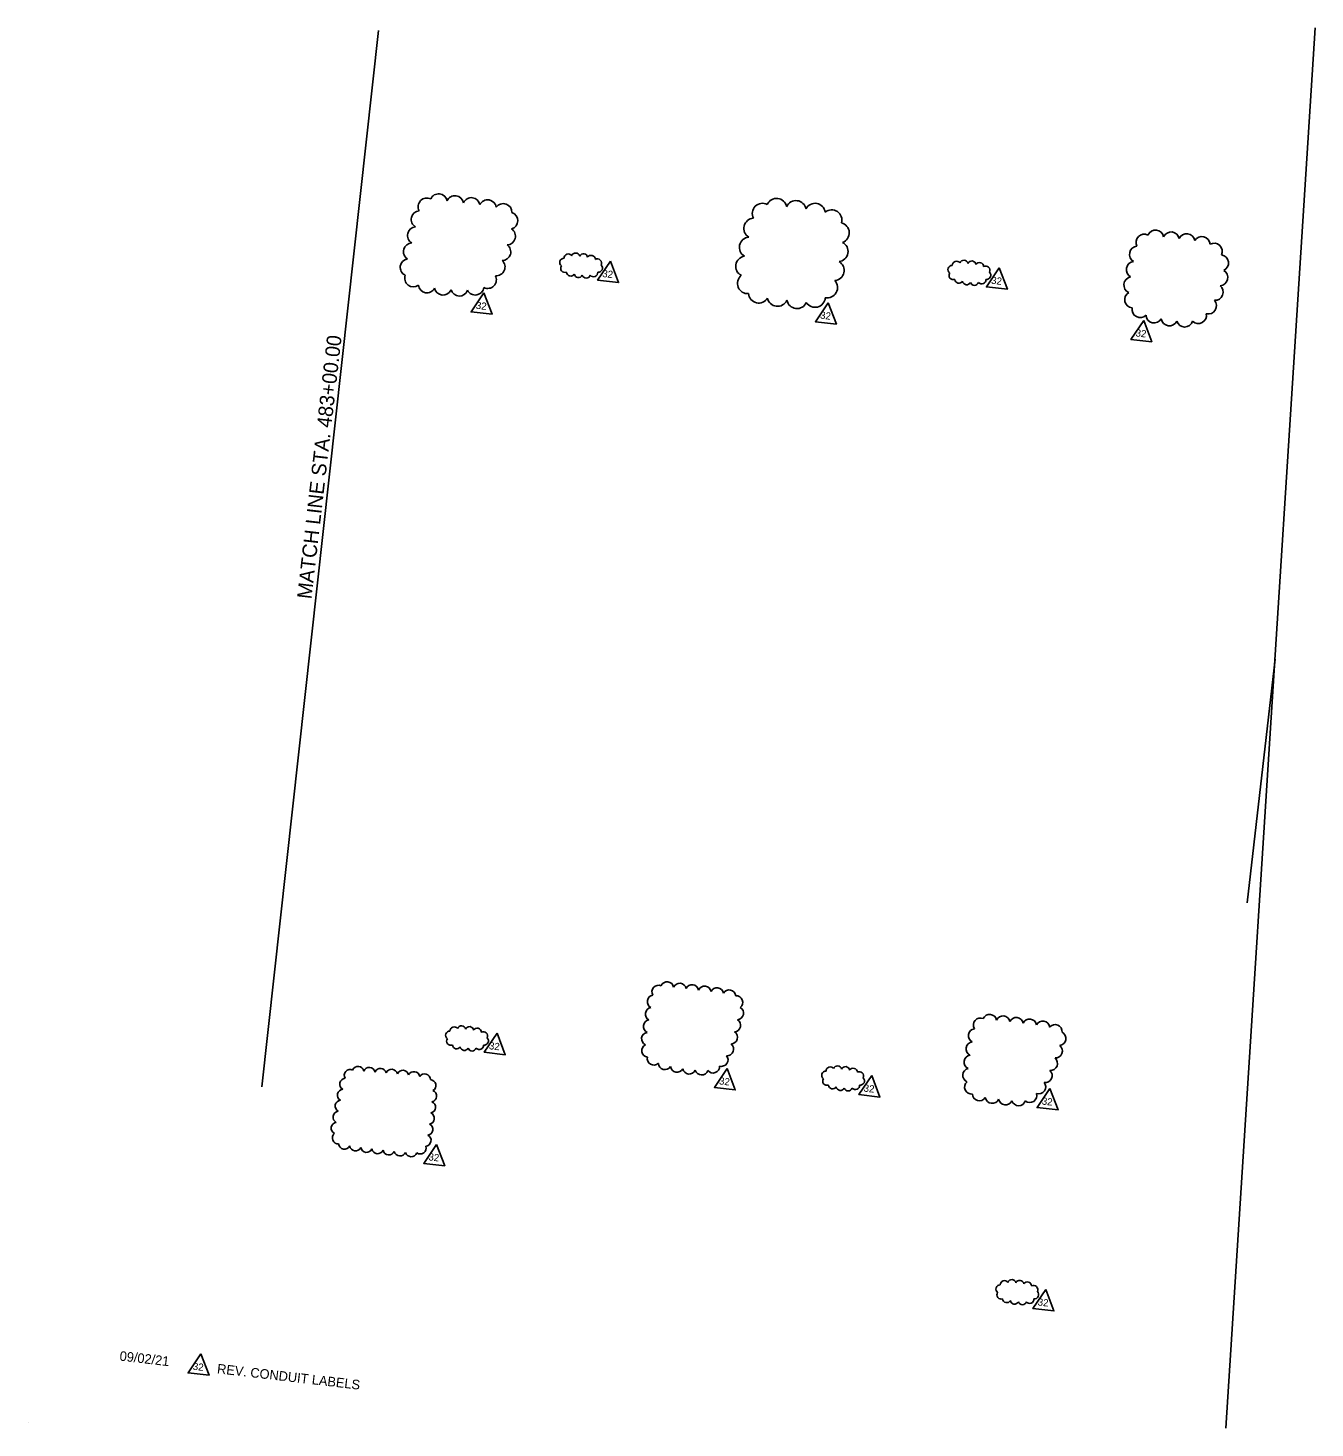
# Model space of a CAD drawing. Extents: x 926540 to 927877, y 636188 to 637075.
# Drawn here: x 926540 to 927245, y 636308 to 637075 of the extents above; entities that cross this region are included whole.
import ezdxf

# ---------------------------------------------------------------- set-up
doc = ezdxf.new("R2010")
doc.units = 0
for name, color, linetype in [('ActivePointCell_dp', 7, 'Continuous'), ('AdhocPoint_dp', 7, 'Continuous'), ('Cloud_dp', 7, 'Continuous'), ('MatchLines_dp', 7, 'Continuous'), ('ScratchEle_dp', 7, 'Continuous'), ('TextLabel', 7, 'Continuous'), ('TextNotes', 7, 'Continuous')]:
    doc.layers.add(name, color=color, linetype=linetype)

msp = doc.modelspace()

# ---------------------------------------------------------------- linework, layer by layer
at = {"layer": 'ActivePointCell_dp'}
msp.add_line((927223.55, 636729.15), (927208.28, 636595.55), dxfattribs=at)
at = {"layer": 'AdhocPoint_dp'}
msp.add_line((926539.98, 636310.75), (926539.98, 636310.75), dxfattribs=at)
at = {"layer": 'Cloud_dp'}
for points in [[(926859.18, 636947.3), (926852.17, 636936.9), (926863.65, 636935.58)], [(927072.35, 636943.6), (927065.33, 636933.2), (927076.81, 636931.88)], [(926789.89, 636929.87), (926782.88, 636919.48), (926794.36, 636918.16)], [(926978.6, 636924.49), (926971.59, 636914.1), (926983.06, 636912.78)], [(927151.52, 636914.77), (927144.5, 636904.38), (927155.98, 636903.06)], [(926797.06, 636524.03), (926790.05, 636513.64), (926801.53, 636512.32)], [(926923.19, 636504.75), (926916.18, 636494.36), (926927.65, 636493.04)], [(927002.47, 636500.82), (926995.46, 636490.43), (927006.93, 636489.11)], [(927100.12, 636493.71), (927093.11, 636483.32), (927104.58, 636482)], [(926763.9, 636463.12), (926756.89, 636452.73), (926768.37, 636451.41)], [(927097.85, 636383.57), (927090.84, 636373.17), (927102.32, 636371.85)]]:
    msp.add_lwpolyline(points, close=True, dxfattribs=at)
for centre, radius, start, end in [((926765.05, 636979.43), 4.75, 10.93299, 155.93299), ((926758.56, 636977.14), 4.75, 62.90771, 207.90771), ((926774.05, 636978.39), 4.75, 10.93299, 155.93299), ((926783.04, 636977.35), 4.75, 10.90569, 155.90569), ((926791.95, 636976.14), 4.75, 8.62888, 153.62888), ((926800.48, 636974.06), 4.75, 358.88682, 143.88682), ((926942.58, 636973.4), 5.61, 62.36437, 207.36437), ((926950.3, 636976.09), 5.61, 10.93299, 155.93299), ((926960.93, 636974.86), 5.61, 10.93299, 155.93299), ((926971.43, 636973.37), 5.61, 7.87137, 152.87137), ((926754.77, 636970.19), 4.75, 94.93587, 239.93587), ((926803.71, 636969.47), 4.74, 286.35637, 71.35637), ((926937.97, 636965.23), 5.61, 93.88155, 238.88155), ((926980.53, 636969.78), 5.61, 344.15324, 129.15324), ((926752.74, 636961.35), 4.75, 94.16753, 239.16753), ((926802.42, 636960.97), 4.75, 271.46132, 56.46132), ((926984.52, 636962.82), 5.61, 290.41714, 75.41714), ((927151.83, 636957.6), 4.51, 62.88116, 207.88116), ((927158, 636959.78), 4.51, 10.93299, 155.93299), ((927166.56, 636958.79), 4.51, 10.93299, 155.93299), ((927175.11, 636957.81), 4.51, 10.93276, 155.93276), ((926750.51, 636952.53), 4.75, 92.37663, 237.37663), ((926799.84, 636952.32), 4.75, 270.35956, 55.35956), ((926935.53, 636954.83), 5.61, 94.68288, 239.68288), ((926983.87, 636952.6), 5.61, 277.34377, 62.34377), ((927148.26, 636951), 4.51, 95.2608, 240.2608), ((927183.37, 636956.28), 4.51, 3.126, 148.126), ((927190.14, 636952.62), 4.51, 335.07037, 120.07037), ((926748.76, 636943.86), 4.75, 99.87844, 244.87844), ((926796.71, 636944.04), 4.75, 263.14775, 48.14775), ((926833.75, 636946.55), 2.31, 88.74525, 233.74525), ((926836.11, 636948.9), 2.31, 35.92386, 180.92386), ((926840.14, 636949.44), 2.31, 14.50632, 159.50632), ((926844.46, 636949.02), 2.31, 9.41904, 154.41904), ((926848.68, 636948.16), 2.31, 2.54325, 147.54325), ((926852.08, 636946.23), 2.31, 333.28416, 118.28416), ((926933.51, 636944.44), 5.61, 98.27866, 243.27866), ((926981.73, 636942.21), 5.61, 274.35644, 59.35644), ((927048.93, 636944.96), 2.31, 35.92386, 180.92386), ((927052.96, 636945.5), 2.31, 14.50632, 159.50632), ((927057.28, 636945.09), 2.31, 9.41904, 154.41904), ((927061.5, 636944.22), 2.31, 2.54325, 147.54325), ((927146.51, 636942.59), 4.51, 96.31557, 241.31557), ((927193.5, 636946.27), 4.51, 295.70955, 80.70955), ((926751.21, 636937.96), 4.74, 160.24757, 305.24757), ((926791.96, 636937.07), 4.75, 243.36136, 28.36136), ((926834.29, 636943.4), 2.31, 145.78075, 290.78075), ((926837.41, 636941.41), 2.31, 184.25215, 329.25215), ((926841.68, 636940.6), 2.31, 189.2335, 334.2335), ((926845.96, 636940.28), 2.31, 197.12777, 342.12777), ((926849.93, 636941.04), 2.31, 219.67619, 4.67619), ((926852.56, 636943.51), 2.31, 261.79822, 46.79822), ((926934.51, 636935.07), 5.61, 129.01072, 274.01072), ((927046.57, 636942.61), 2.31, 88.74525, 233.74525), ((927047.12, 636939.46), 2.31, 145.78075, 290.78075), ((927064.9, 636942.3), 2.31, 333.28416, 118.28416), ((927065.38, 636939.58), 2.31, 261.79822, 46.79822), ((927145.17, 636934.2), 4.51, 100.56808, 245.56808), ((927193.12, 636938.34), 4.51, 273.77906, 58.77906), ((926758.66, 636934.68), 4.75, 187.22135, 332.22135), ((926767.5, 636933.44), 4.75, 191.81536, 336.81536), ((926776.43, 636932.87), 4.75, 195.87631, 340.87631), ((926785.14, 636933.48), 4.75, 207.13598, 352.13598), ((926978.09, 636932.75), 5.61, 258.51154, 43.51154), ((927050.24, 636937.47), 2.31, 184.25215, 329.25215), ((927054.5, 636936.66), 2.31, 189.2335, 334.2335), ((927058.78, 636936.34), 2.31, 197.12777, 342.12777), ((927062.76, 636937.1), 2.31, 219.67619, 4.67619), ((927190.59, 636930.32), 4.51, 266.17559, 51.17559), ((926940.5, 636929.91), 5.61, 184.46176, 329.46176), ((926950.84, 636928.13), 5.61, 190.93299, 335.93299), ((926961.48, 636926.9), 5.61, 190.93299, 335.93299), ((926971.37, 636927.57), 5.61, 211.76008, 356.76008), ((927145.59, 636926.2), 4.51, 120.4093, 265.4093), ((927186.9, 636922.83), 4.51, 256.47374, 41.47374), ((927149.66, 636920.86), 4.51, 169.18242, 314.18242), ((927157.31, 636917.94), 4.51, 183.98609, 328.98609), ((927165.63, 636916.34), 4.51, 189.34077, 334.34077), ((927181.42, 636917.56), 4.51, 226.30855, 11.30855), ((927174.02, 636915.7), 4.51, 196.88086, 341.88086), ((926885.59, 636546.8), 3.61, 66.16681, 211.16681), ((926890.34, 636548.63), 3.61, 10.93299, 155.93299), ((926897.17, 636547.84), 3.61, 10.93299, 155.93299), ((926904, 636547.06), 3.61, 10.93299, 155.93299), ((926910.83, 636546.26), 3.61, 10.77265, 155.77265), ((926917.63, 636545.38), 3.61, 9.44496, 154.44496), ((926924.34, 636544.22), 3.61, 5.96515, 150.96515), ((926883.04, 636541.37), 3.61, 98.49299, 243.49299), ((926928.15, 636541), 3.6, 308.64785, 93.64785), ((926880.91, 636527.79), 3.61, 98.86754, 243.86754), ((926881.96, 636534.58), 3.61, 98.55031, 243.55031), ((926927.01, 636528.4), 3.61, 273.56139, 58.56139), ((926928.59, 636535.07), 3.61, 274.83672, 59.83672), ((927061.99, 636528.58), 3.85, 66.48725, 211.48725), ((927067.05, 636530.54), 3.85, 10.93299, 155.93299), ((927074.35, 636529.7), 3.85, 10.93299, 155.93299), ((927081.66, 636528.86), 3.85, 10.93299, 155.93299), ((927088.95, 636527.99), 3.85, 10.37821, 155.37821), ((926771.22, 636522.92), 2.31, 88.74525, 233.74525), ((926773.58, 636525.26), 2.31, 35.92386, 180.92386), ((926777.61, 636525.81), 2.31, 14.50632, 159.50632), ((926781.93, 636525.39), 2.31, 9.41904, 154.41904), ((926786.15, 636524.53), 2.31, 2.54325, 147.54325), ((926789.55, 636522.6), 2.31, 333.28416, 118.28416), ((926879.92, 636520.99), 3.61, 99.49084, 244.49084), ((926925.27, 636521.77), 3.61, 271.95599, 56.95599), ((927059.25, 636522.75), 3.85, 98.05164, 243.05164), ((927096.15, 636526.89), 3.85, 7.26057, 152.26057), ((927102.95, 636524.92), 3.86, 355.45488, 140.45488), ((927105.02, 636521.19), 3.85, 277.64308, 62.64308), ((926771.76, 636519.76), 2.31, 145.78075, 290.78075), ((926774.89, 636517.78), 2.31, 184.25215, 329.25215), ((926779.15, 636516.97), 2.31, 189.2335, 334.2335), ((926783.43, 636516.64), 2.31, 197.12777, 342.12777), ((926787.4, 636517.41), 2.31, 219.67619, 4.67619), ((926790.03, 636519.88), 2.31, 261.79822, 46.79822), ((926880, 636514.52), 3.61, 116.92954, 261.92954), ((926923.14, 636515.36), 3.61, 266.20829, 51.20829), ((927058.05, 636515.5), 3.85, 98.26885, 243.26885), ((927103.14, 636514.35), 3.85, 266.60888, 51.60888), ((926883.02, 636510.21), 3.61, 168.08703, 313.08703), ((926920.07, 636509.52), 3.61, 253.42311, 38.42311), ((927056.96, 636508.26), 3.85, 99.57101, 244.57101), ((927100.45, 636507.54), 3.85, 265.22097, 50.22097), ((926716.56, 636500.98), 3.23, 64.99514, 209.99514), ((926720.9, 636502.65), 3.23, 12.18547, 157.18547), ((926727.04, 636502.11), 3.23, 12.66095, 157.66095), ((926733.17, 636501.59), 3.23, 12.78637, 157.78637), ((926739.31, 636501.09), 3.23, 12.83368, 157.83368), ((926745.43, 636500.54), 3.23, 11.80852, 156.80852), ((926751.49, 636499.79), 3.23, 9.21133, 154.21133), ((926757.38, 636498.54), 3.23, 1.73557, 146.73557), ((926889.09, 636507.74), 3.61, 182.67259, 327.67259), ((926895.71, 636506.29), 3.61, 187.46969, 332.46969), ((926902.45, 636505.28), 3.61, 190.57583, 335.57583), ((926909.19, 636504.8), 3.61, 196.25971, 341.25971), ((926915.44, 636505.87), 3.61, 218.15512, 3.15512), ((926977.34, 636500.99), 2.31, 88.74525, 233.74525), ((926979.7, 636503.34), 2.31, 35.92386, 180.92386), ((926983.73, 636503.88), 2.31, 14.50632, 159.50632), ((926988.05, 636503.46), 2.31, 9.41904, 154.41904), ((926992.27, 636502.6), 2.31, 2.54325, 147.54325), ((926995.67, 636500.67), 2.31, 333.28416, 118.28416), ((927056.14, 636501.01), 3.85, 102.57543, 247.57543), ((927097.51, 636500.86), 3.85, 262.34768, 47.34768), ((926712.83, 636490.13), 3.23, 95.77156, 240.77156), ((926714.08, 636496.15), 3.23, 95.77156, 240.77156), ((926760.33, 636495.42), 3.23, 300.10417, 85.10417), ((926977.88, 636497.84), 2.31, 145.78075, 290.78075), ((926981, 636495.85), 2.31, 184.25215, 329.25215), ((926985.27, 636495.04), 2.31, 189.2335, 334.2335), ((926989.55, 636494.72), 2.31, 197.12777, 342.12777), ((926993.52, 636495.48), 2.31, 219.67619, 4.67619), ((926996.15, 636497.96), 2.31, 261.79822, 46.79822), ((927057.21, 636494.55), 3.85, 131.13527, 276.13527), ((927093.95, 636494.69), 3.85, 252.63856, 37.63856), ((926711.59, 636484.1), 3.23, 95.92523, 240.92523), ((926760.13, 636483.54), 3.23, 281.46218, 66.46218), ((926760.72, 636489.65), 3.23, 282.53208, 67.53208), ((927061.47, 636490.86), 3.85, 182.12819, 327.12819), ((927068.5, 636489.5), 3.85, 190.93299, 335.93299), ((927075.8, 636488.65), 3.85, 190.93299, 335.93299), ((927083.02, 636488.17), 3.85, 196.44416, 341.44416), ((927089.09, 636489.95), 3.85, 231.06141, 16.06141), ((926710.41, 636478.07), 3.23, 96.96684, 241.96684), ((926759.45, 636477.43), 3.23, 280.85511, 65.85511), ((926709.41, 636472.04), 3.23, 99.25432, 244.25432), ((926758.67, 636471.34), 3.23, 279.61749, 64.61749), ((926710.03, 636466.61), 3.23, 128.77328, 273.77328), ((926713.45, 636463.79), 3.23, 186.98133, 331.98133), ((926719.48, 636462.8), 3.23, 189.43077, 334.43077), ((926754.98, 636461.11), 3.23, 233.01446, 18.01446), ((926757.68, 636465.32), 3.23, 276.58361, 61.58361), ((926725.57, 636461.99), 3.23, 190.34617, 335.34617), ((926731.68, 636461.25), 3.23, 190.88295, 335.88295), ((926737.78, 636460.58), 3.23, 191.54746, 336.54746), ((926743.9, 636460), 3.23, 192.69324, 337.69324), ((926750, 636459.63), 3.23, 195.27085, 340.27085), ((927072.84, 636383.83), 2.31, 88.74525, 233.74525), ((927075.2, 636386.17), 2.31, 35.92386, 180.92386), ((927079.23, 636386.72), 2.31, 14.50632, 159.50632), ((927083.54, 636386.3), 2.31, 9.41904, 154.41904), ((927087.77, 636385.44), 2.31, 2.54325, 147.54325), ((927091.17, 636383.51), 2.31, 333.28416, 118.28416), ((927073.38, 636380.67), 2.31, 145.78075, 290.78075), ((927076.5, 636378.69), 2.31, 184.25215, 329.25215), ((927089.02, 636378.32), 2.31, 219.67619, 4.67619), ((927091.65, 636380.79), 2.31, 261.79822, 46.79822), ((927080.76, 636377.88), 2.31, 189.2335, 334.2335), ((927085.05, 636377.55), 2.31, 197.12777, 342.12777)]:
    msp.add_arc(centre, radius, start, end, dxfattribs=at)
at = {"layer": 'MatchLines_dp'}
msp.add_line((926732.12, 637073.66), (926668.16, 636494.64), dxfattribs=at)
at = {"layer": 'ScratchEle_dp'}
msp.add_line((927196.6, 636307.68), (927245.43, 637075.09), dxfattribs=at)
at = {"layer": 'TextNotes'}
msp.add_lwpolyline([(926634.75, 636348.3), (926627.74, 636337.91), (926639.21, 636336.59)], close=True, dxfattribs=at)

# ---------------------------------------------------------------- texts
at = {"layer": 'Cloud_dp'}
for p in [(926854.6, 636938.62), (927067.76, 636934.92), (926785.31, 636921.19), (926974.01, 636915.81), (927146.93, 636906.09), (926792.48, 636515.35), (926918.6, 636496.07), (926997.88, 636492.14), (927095.53, 636485.03), (926759.32, 636454.44), (927093.27, 636374.89)]:
    msp.add_text('32', height=3.938, rotation=353.43299, dxfattribs=at).set_placement(p)
at = {"layer": 'MatchLines_dp'}
msp.add_text('MATCH LINE STA. 483+00.00', height=8, rotation=83.43299, dxfattribs=at).set_placement((926695.36, 636761.8))
at = {"layer": 'TextLabel'}
for s, p in [('09/02/21', (926589.98, 636344.68)), ('REV. CONDUIT LABELS', (926643.41, 636337.69))]:
    msp.add_text(s, height=5.25, rotation=353.43299, dxfattribs=at).set_placement(p)
at = {"layer": 'TextNotes'}
msp.add_text('32', height=3.938, rotation=353.43299, dxfattribs=at).set_placement((926630.17, 636339.62))

doc.saveas('drawing.dxf')
